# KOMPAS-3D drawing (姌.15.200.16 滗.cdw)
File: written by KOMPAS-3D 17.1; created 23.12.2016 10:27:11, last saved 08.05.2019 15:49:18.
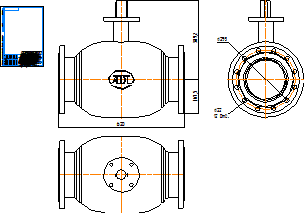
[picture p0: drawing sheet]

Sheet 1: A4, portrait

Title block, sheet 1: name: КШ.15.200.16 фф; material: Внимание! Данный продукт является объектом авторского права ООО «Торговый Дом АДЛ». / Запрещается изменение, копирование, распространение / (в том числе путем копирования на другие сайты и ресурсы в Интернете) / или любое иное использование информации и объектов без предварительного / согласия правообладателя (ООО «Торговый Дом АДЛ»).; sheets: 1; organisation: ООО "Торговый дом АДЛ"; sheet format: A4; stored path: C:\Users\tra\Desktop\2д чертежи\Шаровые краны БИВАЛ\КШ_Бивал_серия_14_15\KOMPAS_2D\КШ.15.200.16 фф.cdw

Views: Вид 1, Проекционный вид 2, Проекционный вид 3
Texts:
  Klimkovich
  ADL
Dimensions and other numbers on the sheet: 620; 389,2; 167,5; 295; 22; 12 Отв.; 1:1; 1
